// Mitsubishi GX Works2 project: MC-17MR-4MT-F430-FX-B例程   PLC: FX1S

PROGRAM MAIN
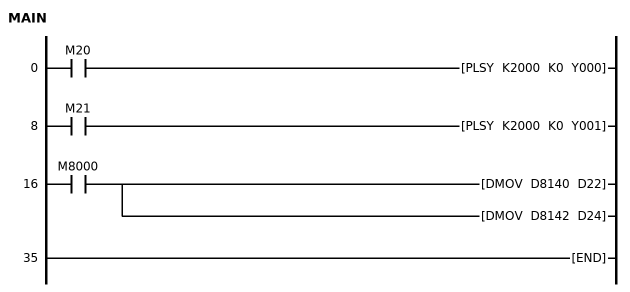
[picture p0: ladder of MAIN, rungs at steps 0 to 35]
0     LD      M20
      PLSY    K2000 K0 Y000
8     LD      M21
      PLSY    K2000 K0 Y001
16    LD      M8000
      DMOV    D8140 D22
      DMOV    D8142 D24
35    END
END_PROGRAM
